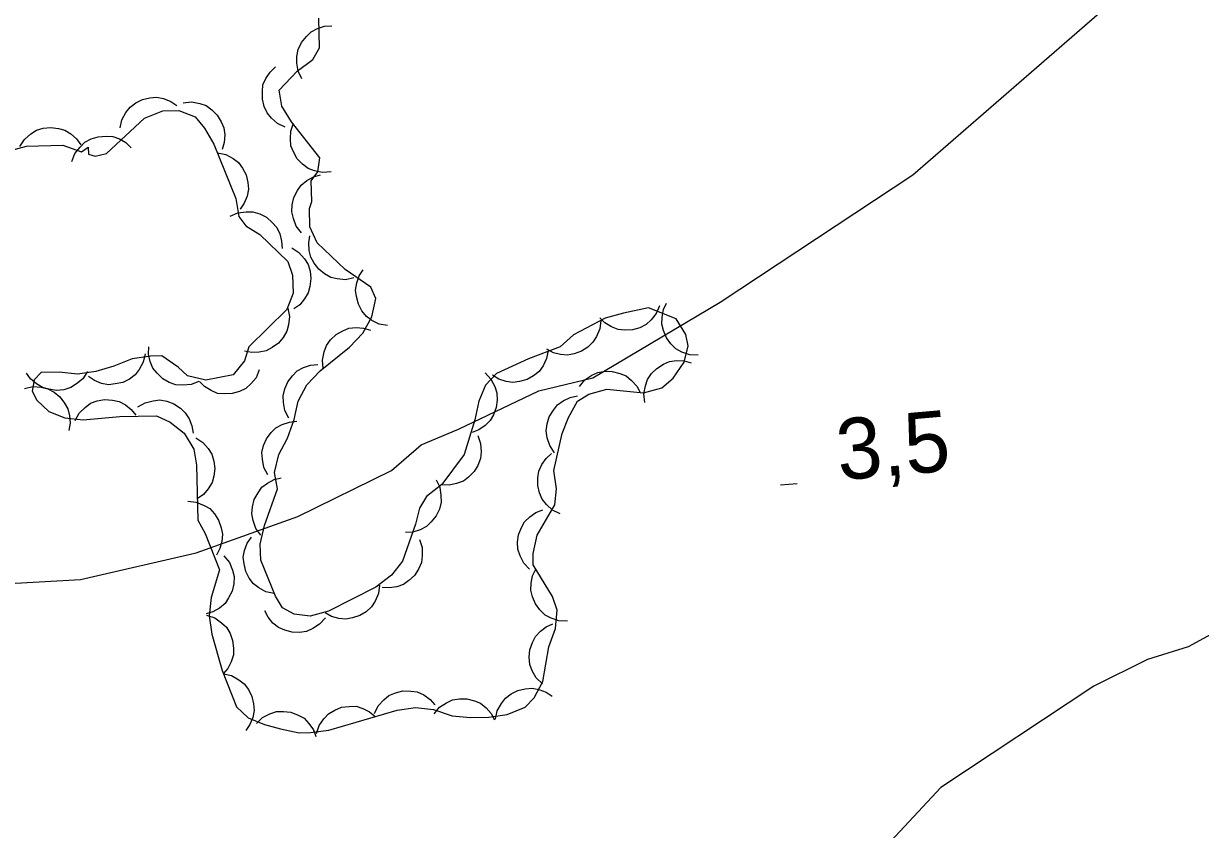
# Model space of a CAD drawing. Extents: x 336540 to 340074, y 5572036 to 5573747.
# Drawn here: x 337408.7 to 337466.6, y 5572687.6 to 5572727.2 of the extents above; entities that cross this region are included whole.
import ezdxf

# ---------------------------------------------------------------- set-up
doc = ezdxf.new("R2010")
doc.units = 0
for name, color, linetype in [('Niveau 2', 7, 'Continuous'), ('Niveau 3', 7, 'Continuous'), ('Niveau 44', 7, 'Continuous')]:
    doc.layers.add(name, color=color, linetype=linetype)

msp = doc.modelspace()

# ---------------------------------------------------------------- linework, layer by layer
at = {"layer": 'Niveau 2'}
for points in [[(337373.07, 5572687.19), (337374.15, 5572689.28), (337377.4, 5572691.98), (337381.52, 5572694.06), (337384.21, 5572694.36), (337391.9, 5572696.29), (337399.22, 5572698.7), (337403.92, 5572699.8), (337408.3, 5572699.67), (337411.5, 5572699.85), (337417.2, 5572701.16), (337422.2, 5572702.95), (337426.81, 5572705.22), (337428.27, 5572706.48), (337430.1, 5572707.25), (337434.05, 5572709.13), (337436.72, 5572709.77), (337442.97, 5572713.5), (337452.46, 5572719.75), (337462.02, 5572728.05), (337464, 5572728.99), (337472.64, 5572731.99)], [(337529.44, 5572723.36), (337527.9, 5572723.63), (337521.87, 5572722.29), (337519.38, 5572721.5), (337509.66, 5572716.42), (337506.14, 5572715.9), (337501.67, 5572713.64), (337499.07, 5572711.8), (337496.17, 5572708.77), (337491.44, 5572705.14), (337487.65, 5572703.25), (337483.48, 5572702.02), (337479.47, 5572701.31), (337475.07, 5572701.08), (337472.64, 5572699.43), (337469.78, 5572698.6), (337466, 5572696.54), (337464.01, 5572695.93), (337461.37, 5572694.61), (337453.84, 5572689.63), (337449.35, 5572684.82)]]:
    msp.add_lwpolyline(points, dxfattribs=at)
at = {"layer": 'Niveau 3'}
msp.add_line((337445.95, 5572704.51), (337446.76, 5572704.58), dxfattribs=at)
at = {"layer": 'Niveau 44'}
for points in [[(337430.38, 5572706.01), (337429.29, 5572704.52), (337428.52, 5572703.94), (337428.19, 5572703.37), (337427.99, 5572702.57), (337427.35, 5572700.76), (337426.81, 5572700.07), (337426.03, 5572699.48), (337423.7, 5572698.3), (337422.8, 5572698.06), (337422.01, 5572698.15), (337421.44, 5572698.47), (337421.09, 5572699.03), (337420.37, 5572700.81), (337420.35, 5572701.6), (337420.55, 5572702.51), (337421.19, 5572704.32), (337421.05, 5572705.11), (337421.26, 5572706.01), (337421.69, 5572706.81), (337422.01, 5572707.72), (337422.21, 5572708.63), (337422.64, 5572709.43), (337423.3, 5572710.12), (337424.74, 5572711.28), (337425.4, 5572711.97), (337425.83, 5572712.77), (337426.03, 5572713.68), (337425.79, 5572714.23), (337424.53, 5572715.1), (337423.15, 5572716.42), (337422.79, 5572717.2), (337422.77, 5572718.1), (337422.88, 5572718.44), (337422.85, 5572719.46), (337423.18, 5572719.91), (337423.28, 5572720.59), (337421.88, 5572722.36), (337421.41, 5572723.14), (337421.28, 5572723.92), (337422.16, 5572724.85), (337422.94, 5572725.43), (337423.26, 5572726), (337423.23, 5572727.46)], [(337422.4, 5572724.48), (337422.22, 5572724.85), (337422.15, 5572725.25), (337422.14, 5572725.58), (337422.22, 5572725.92), (337422.38, 5572726.26), (337422.62, 5572726.56), (337422.85, 5572726.79), (337423.16, 5572726.95), (337423.51, 5572727.06), (337423.87, 5572727.09)], [(337421.58, 5572722.1), (337421.2, 5572722.28), (337420.9, 5572722.55), (337420.68, 5572722.8), (337420.54, 5572723.12), (337420.45, 5572723.47), (337420.45, 5572723.86), (337420.48, 5572724.18), (337420.63, 5572724.5), (337420.83, 5572724.81), (337421.09, 5572725.06)], [(337413.45, 5572722.06), (337413.54, 5572722.46), (337413.74, 5572722.82), (337413.94, 5572723.08), (337414.22, 5572723.29), (337414.55, 5572723.46), (337414.92, 5572723.54), (337415.25, 5572723.58), (337415.59, 5572723.51), (337415.94, 5572723.37), (337416.24, 5572723.17)], [(337416.55, 5572723.3), (337416.97, 5572723.34), (337417.37, 5572723.26), (337417.68, 5572723.16), (337417.97, 5572722.96), (337418.23, 5572722.69), (337418.42, 5572722.36), (337418.56, 5572722.07), (337418.6, 5572721.72), (337418.58, 5572721.34), (337418.48, 5572721)], [(337411.88, 5572721.12), (337411.89, 5572720.78), (337412.23, 5572720.68), (337412.79, 5572720.81), (337414.66, 5572722.54), (337415.56, 5572722.9), (337416.34, 5572722.92), (337417.14, 5572722.6), (337417.6, 5572722.05), (337418.07, 5572721.27), (337419.15, 5572718.59), (337419.29, 5572717.7), (337419.63, 5572717.25), (337420.32, 5572716.82), (337421.7, 5572715.5), (337421.94, 5572714.83), (337421.97, 5572713.93), (337421.65, 5572713.14), (337419.78, 5572711.29), (337419.57, 5572710.61), (337419.02, 5572709.92), (337417.67, 5572709.66), (337416.77, 5572709.87), (337416.31, 5572710.3), (337415.51, 5572710.85), (337414.94, 5572710.84), (337414.05, 5572710.7), (337413.15, 5572710.34), (337412.26, 5572710.09), (337411.36, 5572709.96), (337410.46, 5572710.05), (337409.56, 5572710.03), (337409.23, 5572709.68), (337409.13, 5572709.12), (337409.36, 5572708.67), (337409.94, 5572708.12), (337410.73, 5572707.81), (337411.64, 5572707.71), (337413.44, 5572707.87), (337415.24, 5572707.91), (337415.92, 5572707.59), (337416.61, 5572707.05), (337417.08, 5572706.27), (337417.21, 5572705.48), (337417.28, 5572702.78), (337417.63, 5572702.12), (337418.35, 5572700.33), (337417.93, 5572698.97), (337417.84, 5572698.07), (337417.97, 5572697.17), (337418.47, 5572695.38), (337419.18, 5572693.59), (337419.76, 5572693.05), (337420.56, 5572692.73), (337421.35, 5572692.52), (337422.26, 5572692.32), (337422.82, 5572692.33), (337423.72, 5572692.45), (337427.08, 5572693.43), (337427.98, 5572693.56), (337428.88, 5572693.47), (337429.79, 5572693.16), (337430.69, 5572693.07), (337431.59, 5572693.09), (337432.49, 5572693.22), (337433.38, 5572693.58), (337433.82, 5572694.04), (337434.25, 5572694.84), (337434.55, 5572696.54), (337434.87, 5572697.45), (337434.96, 5572698.35), (337434.72, 5572699.02), (337433.78, 5572700.57), (337433.77, 5572701.14), (337433.97, 5572702.04), (337434.84, 5572703.53), (337434.93, 5572704.32), (337434.8, 5572705.21), (337435.2, 5572707.03), (337435.52, 5572707.82), (337435.95, 5572708.62), (337436.51, 5572708.97), (337437.4, 5572709.22), (337439.21, 5572709.04), (337440.11, 5572709.28), (337440.66, 5572709.75), (337441.2, 5572710.55), (337441.41, 5572711.34), (337441.28, 5572711.9), (337440.81, 5572712.68), (337439.45, 5572713.21), (337438.22, 5572712.96), (337437.32, 5572712.71), (337435.76, 5572711.88), (337435.1, 5572711.3), (337433.54, 5572710.7), (337431.98, 5572709.99), (337431.43, 5572709.41), (337431.11, 5572708.62), (337430.91, 5572707.71), (337430.38, 5572706.01)], [(337423.83, 5572719.9), (337423.41, 5572719.87), (337423.01, 5572719.95), (337422.71, 5572720.07), (337422.42, 5572720.28), (337422.17, 5572720.55), (337421.99, 5572720.88), (337421.86, 5572721.19), (337421.83, 5572721.54), (337421.86, 5572721.91), (337421.97, 5572722.25)], [(337408.52, 5572721.15), (337408.75, 5572721.5), (337409.06, 5572721.77), (337409.33, 5572721.95), (337409.67, 5572722.05), (337410.04, 5572722.09), (337410.42, 5572722.04), (337410.73, 5572721.96), (337411.03, 5572721.77), (337411.31, 5572721.53), (337411.52, 5572721.23)], [(337411.08, 5572720.41), (337411.23, 5572720.8), (337411.48, 5572721.12), (337411.72, 5572721.36), (337412.03, 5572721.52), (337412.38, 5572721.63), (337412.76, 5572721.66), (337413.09, 5572721.64), (337413.42, 5572721.52), (337413.74, 5572721.34), (337414, 5572721.09)], [(337407.94, 5572720.92), (337408.84, 5572721.16), (337410.64, 5572721.21), (337411.55, 5572720.89), (337411.88, 5572721.12)], [(337418.24, 5572720.84), (337418.65, 5572720.76), (337419.01, 5572720.56), (337419.27, 5572720.36), (337419.48, 5572720.08), (337419.65, 5572719.75), (337419.73, 5572719.38), (337419.77, 5572719.05), (337419.7, 5572718.71), (337419.56, 5572718.36), (337419.36, 5572718.06)], [(337422.38, 5572716.9), (337422.12, 5572717.23), (337421.98, 5572717.61), (337421.9, 5572717.93), (337421.92, 5572718.28), (337422, 5572718.64), (337422.18, 5572718.98), (337422.36, 5572719.25), (337422.64, 5572719.47), (337422.96, 5572719.65), (337423.31, 5572719.75)], [(337418.87, 5572717.72), (337419.25, 5572717.89), (337419.66, 5572717.94), (337419.99, 5572717.94), (337420.32, 5572717.84), (337420.65, 5572717.67), (337420.94, 5572717.41), (337421.16, 5572717.17), (337421.31, 5572716.85), (337421.4, 5572716.5), (337421.42, 5572716.14)], [(337424.96, 5572714.69), (337424.55, 5572714.6), (337424.14, 5572714.64), (337423.82, 5572714.71), (337423.51, 5572714.88), (337423.23, 5572715.11), (337423, 5572715.42), (337422.83, 5572715.7), (337422.75, 5572716.04), (337422.73, 5572716.41), (337422.79, 5572716.76)], [(337421.9, 5572716.16), (337422.25, 5572715.94), (337422.52, 5572715.63), (337422.7, 5572715.35), (337422.8, 5572715.02), (337422.84, 5572714.65), (337422.79, 5572714.27), (337422.71, 5572713.95), (337422.53, 5572713.65), (337422.29, 5572713.37), (337422, 5572713.16)], [(337426.61, 5572712.34), (337426.2, 5572712.42), (337425.84, 5572712.6), (337425.57, 5572712.79), (337425.35, 5572713.07), (337425.18, 5572713.39), (337425.08, 5572713.77), (337425.04, 5572714.09), (337425.1, 5572714.44), (337425.22, 5572714.79), (337425.41, 5572715.09)], [(337421.71, 5572713.2), (337421.79, 5572712.79), (337421.74, 5572712.38), (337421.66, 5572712.06), (337421.48, 5572711.76), (337421.24, 5572711.48), (337420.93, 5572711.26), (337420.64, 5572711.1), (337420.3, 5572711.03), (337419.93, 5572711.02), (337419.58, 5572711.09)], [(337440, 5572713.32), (337439.83, 5572712.94), (337439.58, 5572712.62), (337439.33, 5572712.4), (337439.02, 5572712.24), (337438.66, 5572712.14), (337438.28, 5572712.12), (337437.96, 5572712.15), (337437.63, 5572712.28), (337437.31, 5572712.47), (337437.06, 5572712.72)], [(337441.89, 5572710.88), (337441.48, 5572710.91), (337441.09, 5572711.04), (337440.8, 5572711.2), (337440.55, 5572711.44), (337440.33, 5572711.74), (337440.19, 5572712.1), (337440.1, 5572712.41), (337440.12, 5572712.76), (337440.19, 5572713.13), (337440.34, 5572713.45)], [(337437.1, 5572712.59), (337437.05, 5572712.18), (337436.89, 5572711.8), (337436.72, 5572711.52), (337436.47, 5572711.28), (337436.16, 5572711.08), (337435.79, 5572710.96), (337435.47, 5572710.89), (337435.12, 5572710.92), (337434.77, 5572711.01), (337434.45, 5572711.18)], [(337423.44, 5572710.24), (337423.41, 5572710.65), (337423.49, 5572711.05), (337423.61, 5572711.36), (337423.81, 5572711.64), (337424.08, 5572711.9), (337424.41, 5572712.09), (337424.71, 5572712.21), (337425.06, 5572712.25), (337425.43, 5572712.22), (337425.78, 5572712.12)], [(337417.33, 5572709.6), (337416.94, 5572709.45), (337416.53, 5572709.42), (337416.2, 5572709.43), (337415.87, 5572709.55), (337415.55, 5572709.73), (337415.28, 5572710), (337415.07, 5572710.25), (337414.93, 5572710.58), (337414.85, 5572710.94), (337414.86, 5572711.3)], [(337414.68, 5572710.95), (337414.59, 5572710.54), (337414.39, 5572710.19), (337414.19, 5572709.92), (337413.91, 5572709.71), (337413.58, 5572709.55), (337413.21, 5572709.47), (337412.88, 5572709.43), (337412.54, 5572709.5), (337412.19, 5572709.64), (337411.89, 5572709.84)], [(337434.51, 5572711.14), (337434.44, 5572710.73), (337434.26, 5572710.36), (337434.07, 5572710.09), (337433.8, 5572709.87), (337433.48, 5572709.69), (337433.11, 5572709.59), (337432.78, 5572709.54), (337432.44, 5572709.59), (337432.08, 5572709.71), (337431.78, 5572709.9)], [(337439.27, 5572708.56), (337439.22, 5572708.98), (337439.3, 5572709.38), (337439.4, 5572709.69), (337439.6, 5572709.98), (337439.86, 5572710.24), (337440.19, 5572710.44), (337440.48, 5572710.58), (337440.83, 5572710.62), (337441.2, 5572710.61), (337441.55, 5572710.51)], [(337411.84, 5572710.08), (337411.62, 5572709.73), (337411.31, 5572709.47), (337411.03, 5572709.29), (337410.69, 5572709.19), (337410.32, 5572709.15), (337409.95, 5572709.21), (337409.63, 5572709.29), (337409.33, 5572709.47), (337409.05, 5572709.72), (337408.84, 5572710.01)], [(337420.3, 5572710.17), (337420.14, 5572709.78), (337419.88, 5572709.47), (337419.63, 5572709.25), (337419.32, 5572709.1), (337418.96, 5572709), (337418.58, 5572708.99), (337418.25, 5572709.01), (337417.93, 5572709.15), (337417.61, 5572709.35), (337417.36, 5572709.6)], [(337421.76, 5572707.79), (337421.56, 5572708.16), (337421.49, 5572708.56), (337421.47, 5572708.89), (337421.55, 5572709.23), (337421.7, 5572709.57), (337421.93, 5572709.87), (337422.16, 5572710.11), (337422.47, 5572710.28), (337422.82, 5572710.4), (337423.18, 5572710.43)], [(337431.42, 5572710.02), (337431.7, 5572709.71), (337431.89, 5572709.35), (337431.99, 5572709.04), (337432.01, 5572708.68), (337431.96, 5572708.32), (337431.82, 5572707.96), (337431.66, 5572707.68), (337431.41, 5572707.43), (337431.11, 5572707.22), (337430.77, 5572707.08)], [(337436.05, 5572709.35), (337436.32, 5572709.68), (337436.66, 5572709.9), (337436.96, 5572710.04), (337437.3, 5572710.1), (337437.67, 5572710.09), (337438.04, 5572709.99), (337438.35, 5572709.87), (337438.62, 5572709.65), (337438.87, 5572709.37), (337439.04, 5572709.06)], [(337408.75, 5572709.25), (337409.16, 5572709.34), (337409.56, 5572709.31), (337409.89, 5572709.24), (337410.2, 5572709.07), (337410.48, 5572708.84), (337410.71, 5572708.53), (337410.88, 5572708.25), (337410.96, 5572707.91), (337410.99, 5572707.54), (337410.93, 5572707.18)], [(337434.82, 5572706.09), (337434.59, 5572706.44), (337434.47, 5572706.83), (337434.42, 5572707.16), (337434.46, 5572707.51), (337434.57, 5572707.86), (337434.77, 5572708.18), (337434.97, 5572708.44), (337435.26, 5572708.64), (337435.6, 5572708.8), (337435.95, 5572708.88)], [(337411.24, 5572707.67), (337411.44, 5572708.04), (337411.73, 5572708.32), (337412, 5572708.52), (337412.33, 5572708.64), (337412.69, 5572708.7), (337413.08, 5572708.67), (337413.4, 5572708.61), (337413.71, 5572708.45), (337414, 5572708.22), (337414.23, 5572707.94)], [(337414.33, 5572708.34), (337414.68, 5572708.55), (337415.08, 5572708.65), (337415.41, 5572708.69), (337415.75, 5572708.62), (337416.1, 5572708.5), (337416.42, 5572708.28), (337416.66, 5572708.06), (337416.85, 5572707.76), (337416.98, 5572707.42), (337417.04, 5572707.06)], [(337420.72, 5572705), (337420.52, 5572705.37), (337420.45, 5572705.77), (337420.43, 5572706.1), (337420.51, 5572706.44), (337420.66, 5572706.78), (337420.89, 5572707.08), (337421.12, 5572707.32), (337421.43, 5572707.48), (337421.78, 5572707.6), (337422.14, 5572707.64)], [(337417.18, 5572706.83), (337417.53, 5572706.6), (337417.79, 5572706.3), (337417.97, 5572706.02), (337418.07, 5572705.68), (337418.11, 5572705.31), (337418.06, 5572704.93), (337417.98, 5572704.62), (337417.79, 5572704.32), (337417.55, 5572704.04), (337417.25, 5572703.83)], [(337431.05, 5572706.93), (337431.19, 5572706.54), (337431.21, 5572706.13), (337431.19, 5572705.8), (337431.06, 5572705.47), (337430.87, 5572705.16), (337430.59, 5572704.89), (337430.34, 5572704.69), (337430.01, 5572704.57), (337429.64, 5572704.5), (337429.28, 5572704.51)], [(337435.11, 5572703.09), (337434.73, 5572703.27), (337434.43, 5572703.54), (337434.22, 5572703.8), (337434.09, 5572704.12), (337434, 5572704.48), (337434.01, 5572704.86), (337434.05, 5572705.19), (337434.2, 5572705.51), (337434.41, 5572705.81), (337434.68, 5572706.06)], [(337420.38, 5572702.04), (337420.13, 5572702.37), (337420, 5572702.76), (337419.93, 5572703.08), (337419.96, 5572703.43), (337420.05, 5572703.79), (337420.24, 5572704.12), (337420.43, 5572704.39), (337420.71, 5572704.6), (337421.03, 5572704.77), (337421.38, 5572704.86)], [(337429, 5572704.76), (337429.18, 5572704.39), (337429.24, 5572703.99), (337429.25, 5572703.66), (337429.16, 5572703.32), (337429, 5572702.98), (337428.76, 5572702.69), (337428.52, 5572702.46), (337428.21, 5572702.3), (337427.85, 5572702.19), (337427.49, 5572702.17)], [(337416.79, 5572703.71), (337417.2, 5572703.66), (337417.58, 5572703.5), (337417.86, 5572703.34), (337418.1, 5572703.08), (337418.3, 5572702.77), (337418.42, 5572702.4), (337418.49, 5572702.09), (337418.46, 5572701.73), (337418.36, 5572701.38), (337418.19, 5572701.06)], [(337433.6, 5572700.36), (337433.31, 5572700.66), (337433.13, 5572701.02), (337433.02, 5572701.34), (337433.01, 5572701.69), (337433.06, 5572702.05), (337433.2, 5572702.41), (337433.35, 5572702.7), (337433.61, 5572702.94), (337433.91, 5572703.15), (337434.25, 5572703.28)], [(337421.04, 5572699.16), (337420.63, 5572699.25), (337420.27, 5572699.44), (337420.01, 5572699.64), (337419.8, 5572699.92), (337419.63, 5572700.25), (337419.55, 5572700.63), (337419.51, 5572700.95), (337419.58, 5572701.29), (337419.71, 5572701.64), (337419.91, 5572701.94)], [(337428.18, 5572701.83), (337428.31, 5572701.43), (337428.32, 5572701.02), (337428.28, 5572700.69), (337428.14, 5572700.37), (337427.94, 5572700.06), (337427.66, 5572699.8), (337427.39, 5572699.61), (337427.06, 5572699.5), (337426.69, 5572699.44), (337426.34, 5572699.46)], [(337418.56, 5572701.02), (337418.83, 5572700.7), (337418.98, 5572700.32), (337419.06, 5572700), (337419.04, 5572699.65), (337418.97, 5572699.29), (337418.79, 5572698.95), (337418.62, 5572698.67), (337418.34, 5572698.45), (337418.02, 5572698.26), (337417.68, 5572698.16)], [(337435.46, 5572697.8), (337435.04, 5572697.83), (337434.66, 5572697.96), (337434.36, 5572698.11), (337434.11, 5572698.36), (337433.89, 5572698.66), (337433.75, 5572699.01), (337433.66, 5572699.33), (337433.68, 5572699.68), (337433.75, 5572700.04), (337433.9, 5572700.37)], [(337426.22, 5572699.57), (337426.16, 5572699.16), (337426, 5572698.79), (337425.82, 5572698.51), (337425.56, 5572698.27), (337425.25, 5572698.08), (337424.88, 5572697.97), (337424.56, 5572697.9), (337424.21, 5572697.94), (337423.85, 5572698.04), (337423.54, 5572698.22)], [(337417.71, 5572698.1), (337418.11, 5572697.97), (337418.44, 5572697.73), (337418.68, 5572697.51), (337418.86, 5572697.2), (337418.99, 5572696.86), (337419.03, 5572696.48), (337419.03, 5572696.15), (337418.92, 5572695.81), (337418.75, 5572695.48), (337418.52, 5572695.21)], [(337423.55, 5572697.97), (337423.27, 5572697.66), (337422.93, 5572697.44), (337422.63, 5572697.3), (337422.28, 5572697.25), (337421.91, 5572697.26), (337421.55, 5572697.37), (337421.24, 5572697.49), (337420.97, 5572697.71), (337420.73, 5572698), (337420.57, 5572698.31)], [(337434.23, 5572694.73), (337433.93, 5572695.02), (337433.73, 5572695.37), (337433.61, 5572695.68), (337433.58, 5572696.03), (337433.62, 5572696.4), (337433.74, 5572696.76), (337433.89, 5572697.06), (337434.13, 5572697.31), (337434.42, 5572697.53), (337434.75, 5572697.68)], [(337418.54, 5572695.22), (337418.94, 5572695.13), (337419.3, 5572694.93), (337419.56, 5572694.73), (337419.77, 5572694.44), (337419.94, 5572694.11), (337420.02, 5572693.74), (337420.05, 5572693.42), (337419.98, 5572693.07), (337419.84, 5572692.72), (337419.64, 5572692.43)], [(337425.97, 5572693.27), (337426.15, 5572693.65), (337426.43, 5572693.94), (337426.68, 5572694.15), (337427.01, 5572694.29), (337427.37, 5572694.38), (337427.75, 5572694.37), (337428.07, 5572694.33), (337428.39, 5572694.18), (337428.7, 5572693.96), (337428.94, 5572693.7)], [(337431.93, 5572692.99), (337432.01, 5572693.4), (337432.21, 5572693.76), (337432.41, 5572694.02), (337432.69, 5572694.23), (337433.02, 5572694.4), (337433.39, 5572694.48), (337433.72, 5572694.52), (337434.06, 5572694.45), (337434.41, 5572694.32), (337434.71, 5572694.12)], [(337428.9, 5572693.25), (337429.17, 5572693.57), (337429.51, 5572693.79), (337429.8, 5572693.94), (337430.15, 5572693.99), (337430.52, 5572693.99), (337430.89, 5572693.89), (337431.19, 5572693.77), (337431.47, 5572693.54), (337431.71, 5572693.27), (337431.88, 5572692.95)], [(337420.16, 5572692.78), (337420.46, 5572693.07), (337420.82, 5572693.25), (337421.14, 5572693.36), (337421.49, 5572693.37), (337421.85, 5572693.33), (337422.21, 5572693.18), (337422.5, 5572693.03), (337422.74, 5572692.78), (337422.96, 5572692.47), (337423.09, 5572692.14)], [(337423.12, 5572692.28), (337423.25, 5572692.67), (337423.48, 5572693.01), (337423.71, 5572693.25), (337424.01, 5572693.43), (337424.35, 5572693.57), (337424.73, 5572693.61), (337425.06, 5572693.62), (337425.4, 5572693.51), (337425.73, 5572693.35), (337426, 5572693.12)]]:
    msp.add_lwpolyline(points, dxfattribs=at)

# ---------------------------------------------------------------- texts
at = {"layer": 'Niveau 3'}
msp.add_text('3,5    ', height=2.9999, rotation=5.04747, dxfattribs=at).set_placement((337448.83, 5572704.73))

doc.saveas('drawing.dxf')
